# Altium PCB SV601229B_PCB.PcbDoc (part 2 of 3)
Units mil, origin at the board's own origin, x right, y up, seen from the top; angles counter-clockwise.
Board outline 3875 x 2375 mil, 10 copper layers (Top Layer, MidLayer1, MidLayer2, MidLayer3, MidLayer4, MidLayer5, MidLayer6, MidLayer7, MidLayer8, Bottom Layer), stack 98 mil thick; 184 components, 75 nets, 694 pads, 496 vias.
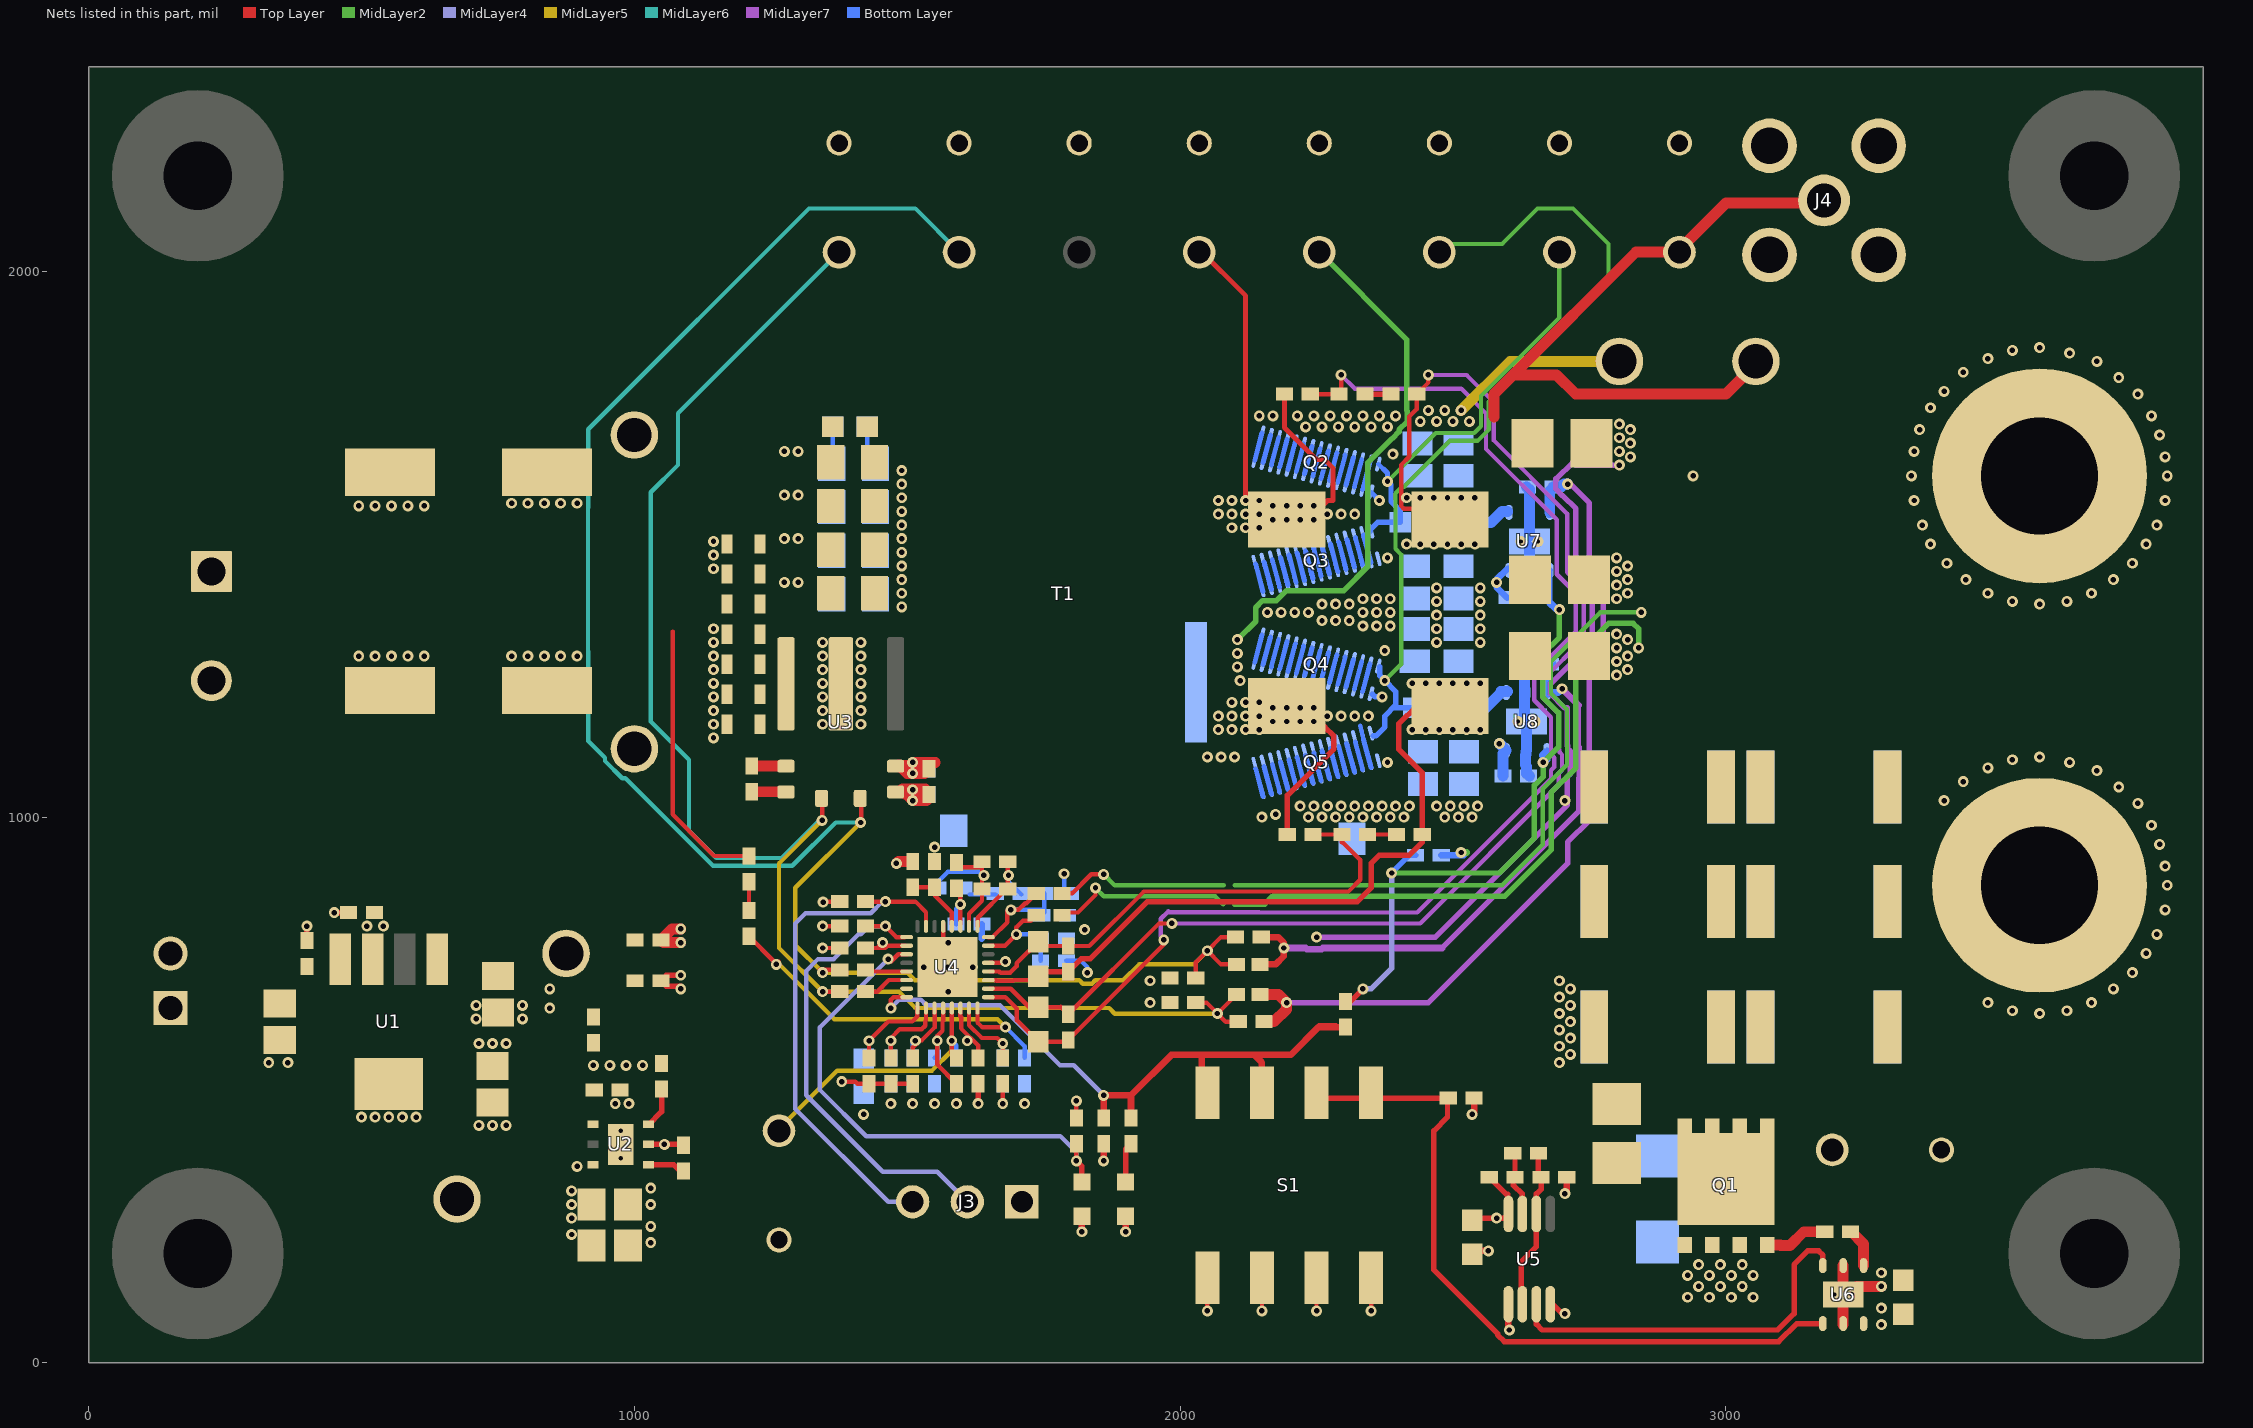
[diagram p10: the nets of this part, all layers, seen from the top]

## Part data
C1 C6 C7 C9 C10: "CAP, CERM, 2.2 µF, 16 V, +/- 10%, X7R, 0805", Cap_Case=0805, Manufacturer=Kemet, Supplier Part Number 1=399-3523-1-ND, TempCo=X7R, Tolerance_%=10, Value1="0.008 ohm", Value2=16V, ValueDisplayed=2.2µF
C2 C19 C53: "CAP, CERM, 0.1 µF, 50 V, +/- 10%, X7R, 0402", Cap_Case=0402, Manufacturer=TDK, Supplier Part Number 1=445-5932-1-ND, TempCo=X7R, Tolerance_%=10, Value1="0.039064 ohm", Value2=50V, ValueDisplayed=0.1µF
C3 C4: "CAP, AL, 22 µF, 100 V, +/- 20%,  ohm, SMD", Cap_Case=HA0, Manufacturer=Chemi-Con, Supplier Part Number 1=565-2160-1-ND, Tolerance_%=20, Value1=Unknown, Value2=100V, ValueDisplayed=22µF
C5 C8 C39 C41 C51: "CAP, CERM, 0.22 µF, 16 V, +/- 10%, X7R, 0402", Cap_Case=0402, Manufacturer=TDK, Supplier Part Number 1=445-5936-1-ND, TempCo=X7R, Tolerance_%=10, Value1=Unknown, Value2=16V, ValueDisplayed=0.22µF
C11 C35: "CAP, CERM, 0.01 µF, 16 V, +/- 10%, X7R, 0402", Cap_Case=0402, Manufacturer=TDK, Supplier Part Number 1=445-1262-1-ND, TempCo=X7R, Tolerance_%=10, Value1="0.0623 ohm", Value2=16V, ValueDisplayed=0.01µF
C12 C13 C14 C15 C16 C17 C18: "CAP, CERM, 0.1uF, 100V, +/-10%, X7R, 0603", Cap_Case=0603, Manufacturer=MuRata, Supplier Part Number 1=490-6439-1-ND, TempCo=X7R, Tolerance_%=10, Value1=Unknown, Value2=100V, ValueDisplayed=0.1µF
C20 C21 C22 C23 C54 C55 C56 C57: "CAP, CERM, 4.7uF, 50V, +/-10%, X5R, 0805", Cap_Case=0805, Manufacturer=TDK, Supplier Part Number 1=445-5980-1-ND, TempCo=X5R, Tolerance_%=10, Value1=Unknown, Value2=50V, ValueDisplayed=4.7µF
C24 C25 C26 C28: "CAP, CERM, 1uF, 10V, +/-10%, X5R, 0402", Cap_Case=0402, Manufacturer=MuRata, Supplier Part Number 1=490-3890-1-ND, TempCo=X5R, Tolerance_%=10, Value1=Unknown, Value2=10V, ValueDisplayed=1µF
C27 C38 C40: "CAP, CERM, 10 pF, 50 V, +/- 5%, C0G/NP0, 0402", Cap_Case=0402, Manufacturer=MuRata, Supplier Part Number 1=81-GRM1555C1H100JA1D, TempCo=C0G/NP0, Tolerance_%=5, Value1=Unknown, Value2=50V, ValueDisplayed=10pF
C29 C30: "CAP, CERM, 0.33 µF, 16 V, +/- 10%, X7R, 0603", Cap_Case=0603, Manufacturer=MuRata, Supplier Part Number 1=490-3294-1-ND, TempCo=X7R, Tolerance_%=10, Value1=Unknown, Value2=16V, ValueDisplayed=0.33µF
C31 C37: "CAP, CERM, 0.22 µF, 16 V, +/- 10%, X7R, 0603", Cap_Case=0603, Manufacturer=Kemet, Supplier Part Number 1=399-5619-1-ND, TempCo=X7R, Tolerance_%=10, Value1=Unknown, Value2=16V, ValueDisplayed=0.22µF
C32 C33 C34 C36: "CAP, TA, 150 µF, 6.3 V, +/- 20%, 0.025 ohm, SMD", Cap_Case=3528-21, Manufacturer=Kemet, Supplier Part Number 1=399-5753-1-ND, Tolerance_%=20, Value1="0.025 ohm", Value2=6.3V, ValueDisplayed=150µF
C42 C43 C44 C45 C46 C47 C48 C49: "CAP, CERM, 47 µF, 10 V, +/- 20%, X5R, 0805", Cap_Case=0805, Manufacturer=MuRata, TempCo=X5R, Tolerance_%=20, Value1=Unknown, Value2=10V, ValueDisplayed=47µF
C50: "CAP, CERM, 680 pF, 25 V, +/- 5%, C0G/NP0, 0402", Cap_Case=0402, Manufacturer=MuRata, Supplier Part Number 1=GRM1555C1E681JA01D-ND, TempCo=C0G/NP0, Tolerance_%=5, Value1=Unknown, Value2=25V, ValueDisplayed=680pF
C52: "CAP, CERM, 4700 pF, 16 V, +/- 10%, X7R, 0402", Cap_Case=0402, Manufacturer=MuRata, Supplier Part Number 1=GRM155R71C472KA01D-ND, TempCo=X7R, Tolerance_%=10, Value1=Unknown, Value2=16V, ValueDisplayed=4700pF
D1 D2: "LED, Green, SMD", Color=Green, Manufacturer="Wurth Elektronik eiSos", Supplier Part Number 1=732-4971-1-ND, Value1=W, Value2=3.2V
D3 D4: "Diode, Schottky, 45 V, 0.1 A, SOD-523", Manufacturer="Diodes Inc.", Supplier Part Number 1=SDM10U45-FDICT-ND, Value1=0.1A, Value2=0.58V
D5: "Diode, Zener, 12 V, 1.5 W, SMA", Manufacturer="ON Semiconductor", Power_W=1.5, Supplier Part Number 1=1SMA5927BT3GOSCT-ND, Value1=1.5W
H1 H2 H3 H4: "Machine Screw, Round, #4-40 x 1/4, Nylon, Philips panhead", DigiKeyPartNumber=H542-ND, Manufacturer="B&F Fastener Supply"
J1: "Terminal Block, 5.08 mm, 2x1, TH", Color=Green, Current_A=17.5, Manufacturer="Phoenix Contact", Supplier Part Number 1=277-1263-ND, Voltage_V=400
J2: "Terminal Block, 2x1, 2.54mm, TH", Manufacturer="TE Connectivity", Supplier Part Number 1=A98333-ND
J3: "Header, 2.54 mm, 3x1, Tin, TH", Manufacturer=Samtec, Supplier Part Number 1=SAM1035-03-ND
J4: "Connector, TH, SMA", Manufacturer="Emerson Network Power", Supplier Part Number 1=J500-ND
J5 J6: "Standard Banana Jack, Uninsulated, 5.5mm", Manufacturer=Keystone, Supplier Part Number 1=575-4K-ND
L1 L2: "Inductor, Shielded Drum Core, Ferrite, 250 nH, 27 A, 0.00037 ohm, SMD", Manufacturer="Wurth Elektronik", Supplier Part Number 1=732-2998-1-ND, Value1="0.00037 ohm", Value2=27A, ValueDisplayed=250nH
LBL1: library part THT-14-423-10, "Thermal Transfer Printable Labels, 0.650\" W x 0.200\" H - 10,000 per roll", Manufacturer=Brady, Supplier Part Number 1=2065596
LOGO1: library part IEC_HighVoltage, "IEC 61010-1 High Voltage Warning"
Logo2 Logo6: library part TI_Logo, "Texas Instrument Corporate Signature"
Logo3: library part FCC_disclaimer, "FCC_disclaimer"
LOGO4: library part IEC_HotSurface, "IEC 61010-1 Hot Surface Warning"
NT1 NT2 NT3 NT4: library part Net-Tie, "Single point connection between nets."
Q1: "MOSFET, N-CH, 25 V, 100 A, SON 5x6mm", Alternate Manufacturer=None, Manufacturer="Texas Instruments", Supplier Part Number 1=296-24517-1-ND, Value1="0.0021 ohm", Value2="14 nC"
Q2 Q3 Q4 Q5: "MOSFET, N-CH, 30 V, 60 A, 6.05x2.3mm", Alternate Manufacturer=None, Manufacturer=EPC, Value1="? ohm", Value2="20 nC"
R1 R2 R3: "RES, 0.1, 1%, 0.125 W, 0402", Manufacturer=Panasonic, Power_W=0.125, Supplier Part Number 1=P.10AKCT-ND, TempCo="300 ppm/C", Tolerance_%=1, Value1=1%, Value2=0.125W, Value_Code=R100, ValueDisplayed=0.1
R4 R8 R9 R27 R28: "RES, 2.74 k, 1%, 0.063 W, 0402", Manufacturer=Vishay-Dale, Power_W=0.063, Supplier Part Number 1=541-2.74KLCT-ND, TempCo="100 ppm/C", Tolerance_%=1, Value1=1%, Value2=0.063W, Value_Code=2k74, ValueDisplayed=2.74k
R5 R6: "RES, 47 k, 5%, 0.063 W, 0402", Manufacturer=Vishay-Dale, Power_W=0.063, Supplier Part Number 1=541-47KJCT-ND, TempCo="200 ppm/C", Tolerance_%=5, Value1=5%, Value2=0.063W, Value_Code=47k0, ValueDisplayed=47k
R7 R55 R57: "RES, 150 k, 1%, 0.1 W, 0603", Manufacturer=Vishay-Dale, Power_W=0.1, Supplier Part Number 1=541-150KHCT-ND, TempCo="100 ppm/C", Tolerance_%=1, Value1=1%, Value2=0.1W, Value_Code=150k
R10 R11 R13 R25 R26 R58 R59 R67 R68: "RES, 10.0, 1%, 0.063 W, 0402", Manufacturer=Vishay-Dale, Power_W=0.063, Supplier Part Number 1=541-10.0LCT-ND, TempCo="100 ppm/C", Tolerance_%=1, Value1=1%, Value2=0.063W, Value_Code=10R0, ValueDisplayed=10.0
R12 R18 R22 R23 R41 R50 R52 R60: "RES, 10.0 k, 1%, 0.063 W, 0402", Manufacturer=Vishay-Dale, Power_W=0.063, Supplier Part Number 1=541-10.0KLCT-ND, TempCo="100 ppm/C", Tolerance_%=1, Value1=1%, Value2=0.063W, Value_Code=10k0, ValueDisplayed=10.0k
R14 R54: "RES, 100 k, 1%, 0.063 W, 0402", Manufacturer=Vishay-Dale, Power_W=0.063, Supplier Part Number 1=541-100KLCT-ND, TempCo="100 ppm/C", Tolerance_%=1, Value1=1%, Value2=0.063W, Value_Code=100k
R15 R31 R32 R33 R56: "RES, 39.2 k, 1%, 0.063 W, 0402", Manufacturer=Vishay-Dale, Power_W=0.063, Supplier Part Number 1=541-39.2KLCT-ND, TempCo="100 ppm/C", Tolerance_%=1, Value1=1%, Value2=0.063W, Value_Code=39k2, ValueDisplayed=39.2k
R16: "RES, 5.11 k, 1%, 0.063 W, 0402", Manufacturer=Vishay-Dale, Power_W=0.063, Supplier Part Number 1=541-5.11KLCT-ND, TempCo="100 ppm/C", Tolerance_%=1, Value1=1%, Value2=0.063W, Value_Code=5k11, ValueDisplayed=5.11k
R17: "RES, 178 k, 1%, 0.063 W, 0402", Manufacturer=Vishay-Dale, Power_W=0.063, Supplier Part Number 1=541-178KLCT-ND, TempCo="100 ppm/C", Tolerance_%=1, Value1=1%, Value2=0.063W, Value_Code=178k
R19 R51 R53: "RES, 24 k, 5%, 0.063 W, 0402", Manufacturer=Vishay-Dale, Power_W=0.063, Supplier Part Number 1=541-24KJCT-ND, TempCo="200 ppm/C", Tolerance_%=5, Value1=5%, Value2=0.063W, Value_Code=24k0, ValueDisplayed=24k
R20 R21: "RES, 20.0 k, 1%, 0.063 W, 0402", Manufacturer=Vishay-Dale, Power_W=0.063, Supplier Part Number 1=541-20.0KLCT-ND, TempCo="100 ppm/C", Tolerance_%=1, Value1=1%, Value2=0.063W, Value_Code=20k0, ValueDisplayed=20.0k
R24: "RES, 470, 5%, 0.063 W, 0402", Manufacturer=Vishay-Dale, Power_W=0.063, Supplier Part Number 1=541-470JCT-ND, TempCo="200 ppm/C", Tolerance_%=5, Value1=5%, Value2=0.063W, Value_Code=470R, ValueDisplayed=470
R29 R30: "RES, 3.32 k, 1%, 0.063 W, 0402", Manufacturer=Vishay-Dale, Power_W=0.063, Supplier Part Number 1=541-3.32KLCT-ND, TempCo="100 ppm/C", Tolerance_%=1, Value1=1%, Value2=0.063W, Value_Code=3k32, ValueDisplayed=3.32k
R34 R35 R36 R37 R38 R39 R42 R43 R44 R45 R46 R47: "RES, 0.04, 1%, 3 W, 2512", Manufacturer=Bourns, Power_W=3, Supplier Part Number 1=CRA2512-FZ-R040ELFCT-ND, TempCo="75 ppm/C", Tolerance_%=1, Value1=1%, Value2=3W, Value_Code=R040, ValueDisplayed=0.04
R40 R61 R62 R63 R64: "RES, 1.00 k, 1%, 0.063 W, 0402", Manufacturer=Vishay-Dale, Power_W=0.063, Supplier Part Number 1=541-1.00KLCT-ND, TempCo="100 ppm/C", Tolerance_%=1, Value1=1%, Value2=0.063W, Value_Code=1k00, ValueDisplayed=1.00k
R48 R49: "RES, 2.2, 5%, 0.1 W, 0603", Manufacturer=Vishay-Dale, Power_W=0.1, Supplier Part Number 1=541-2.2GCT-ND, TempCo="200 ppm/C", Tolerance_%=5, Value1=5%, Value2=0.1W, Value_Code=2R20, ValueDisplayed=2.2
RT1 RT2: "Thermistor NTC, 10k ohm, 5%, 0402", Manufacturer=MuRata, Power_W=0.1, Supplier Part Number 1=490-2414-1-ND, Tolerance_%=5
S1: "Switch, DPST, 2 Pos, 0.1 A, 50 VDC, SMD", CurrentRating_mA=100, Manufacturer="CTS Electrocomponents", Supplier Part Number 1=CT204212ST-ND
T1: library part T_ER18_5to1_A, "Transformer ER18 5:1 turns ratio", Alternate Manufacturer=-, Manufacturer=Ferroxcube
TP1 TP4 TP12: "Test Point, Multipurpose, Black, TH", Manufacturer=Keystone, Supplier Part Number 1=5011K-ND
TP2 TP3 TP14: "Test Point, Multipurpose, Red, TH", Manufacturer=Keystone, Supplier Part Number 1=5010K-ND
TP5 TP6 TP7 TP8 TP9 TP10 TP11 TP13: "PIGTAIL", Manufacturer="Texas Instruments"
TP15 TP16: "Testpoint PCB footprint for pigtail probe", Alternate Manufacturer=-, Manufacturer="Used in BOM report", PartNumber=N/A
U1: "500mA Low Dropout CMOS Linear Regulators Stable with Ceramic Output Capacitors, 5-pin SOT-223, Pb-Free", Manufacturer="Texas Instruments", PackageTopMarking=XYTT*LJZB, PowerWise=Y, Supplier Part Number 1=LP38693MP-5.0TR-ND
U2: "Micropower 250 mA Low-Noise Ultra Low-Dropout Regulator, 6-pin LLP, Pb-Free", Manufacturer="Texas Instruments", PackageTopMarking=ZXYTT*L014A, PowerWise=N, Supplier Part Number 1=LP2992AILD-3.3TR-ND
U3: "80V, 10A GaN Half-Bridge Power Stage, MOF0009A (QFM-9)", Alternate Manufacturer="Texas Instruments", Alternate PartNumber=LMG5200MOFT
U4: "Half-Bridge D-CAP+TM Controller for 48V GaN DC/DC Converter, RSM0032B", Alternate Manufacturer="Texas Instruments"
U5: "CMOS Timer, 8-pin Mini SOIC, Pb-Free", Manufacturer="Texas Instruments", PackageTopMarking=ZXTT*ZC5, PowerWise=N, Supplier Part Number 1=LMC555CMMTR-ND
U6 U7 U8: "Single-Channel High-Speed Low-Side Gate Driver with 4-A Peak Source and 8-A Peak Sink, DRS0006A", Alternate Manufacturer="Texas Instruments", Alternate PartNumber=UCC27512DRST
ZZ1: library part AssemblyNoteLabel, Alternate Manufacturer=-

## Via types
v1: diameter 20, hole 10, Top Layer to Bottom Layer, tented both sides, 459 vias
v2: diameter 20, hole 10, Top Layer to Bottom Layer, 29 vias
v3: diameter 19.68, hole 7.87, Top Layer to Bottom Layer, 8 vias

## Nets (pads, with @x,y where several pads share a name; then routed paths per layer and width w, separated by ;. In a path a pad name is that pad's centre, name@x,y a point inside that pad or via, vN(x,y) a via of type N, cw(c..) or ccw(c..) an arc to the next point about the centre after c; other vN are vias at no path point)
AGND: C1.2 C2.2 C5.1 C6.2 C7.2 C8.1 C9.2 C10.2 C11.2 C24.1 C25.2 C28.1 C31.2 C35.2 C51.2 C52.1 D1.1 D2.1 J2.1 J3.1 NT3.1 NT4.2 R22.2 R23.1 R31.1 R41.2 R50.2 R51.2 R53.2 R54.2 R56.2 R57.1 R62.2 R64.2 TP1.1 TP16.2 U1.5 U2.2 U2.7 U4.29 U4.33 U5.1 | length 559.2
  Top Layer w8: v1(1345,760) C24.1@1376.38,760 ; U4.29@1565.87,803.62 1565.87,743.89 ccw(c1592.75,743.89) v2(1573.74,724.88)
  Top Layer w10: C2.2@400,773.62 v1(400,800) ; v1(450,825) C5.1@476.38,825 ; U2.2@1025.98,400 1085,400 C11.2@1090,395 ; v2(1573.74,724.88) U4.33@1597.36,748.5 ; v1(1630,475) C28.1@1630,511.38
  Top Layer w12: v1(1820,240) D1.1@1820,268.5 ; v1(1860,370) R23.1@1860,401.38 ; v1(1900,240) D2.1@1900,268.5 ; C31.2@2535,200 2540,205 v1(2565,205) ; v1(2535,455) 2538.62,458.62 R31.1@2538.62,485 ; U5.1@2601.61,107.32 2601.61,61.61 v1(2603.23,60) ; v1(2705,310) 2708.62,313.62 C35.2@2708.62,340
  Bottom Layer w12: 1636.73,776.73 C51.2@1636.73,803.62
  other v1: 1030,220 1030,250 1030,290 1030,320 1055,400 715,435 740,435 765,435 500,450 525,450 550,450 575,450 600,450 1420,455 965,475 990,475 1470,475 1510,475 1550,475 1590,475 1715,475 330,550 365,550 710,630 795,630 710,655 795,655 1550,945
  other v2: 1945,660 1575,680 1945,700 1530,725 1620,725 1575,770 1825,793.62
  other v3: 975,375 975,425
CTRL_COMP: C27.1 R16.1 R18.2 R52.2 U4.26 | length 270
  Top Layer w8: R16.1@1590.52,916.73 1599.14,908.1 1636.9,908.1 C27.1@1636.9,868.1 1636.9,846.48 1613.11,822.69 U4.26@1613.11,803.62
  Bottom Layer w8: R52.2@1556.38,870 1556.38,881.38 1574.54,899.54 1634.08,899.54 v1(1640.52,893.1)
CTRL_CSP1: C30.1 R21.2 R27.1 RT1.2 U4.17 | length 2467
  Top Layer w8: U4.17@1652.48,669.76 1679.84,669.76 1700.65,648.95 1700.65,627.85 C30.1@1740,588.5 1792.13,588.5 R21.2@1795,591.38 1970,766.38 v1(1970,775) ; R27.1@2238.62,1775 RT1.2@2285,1775 ; RT1.2@2290,1780 2295,1785 v1(2295,1810)
  MidLayer7 w8: v1(1970,775) 1964.6,780.4 1964.6,813.45 1978.28,827.12 ; 1980,825.4 2144.6,825.4 2145,825 2434.58,825 2679.58,1070 2679.58,1085.73 2685.4,1091.55 2685.4,1108.45 2680.4,1113.45 2680.4,1117.9 2679.58,1118.72 2679.58,1183.01 2648.8,1213.79 2648.8,1263.8 2725,1340 2725,1410 2690,1445 2690,1545 2560.6,1674.4 2560.6,1739.4 2515,1785 2320,1785 v1(2295,1810)
CTRL_CSP2: C29.1 R20.2 R28.1 RT2.2 U4.20 | length 908.6
  Top Layer w8: U4.20@1652.48,717.01 1669.14,717.01 1669.14,715.6 1670.23,715.6 1671.23,714.6 1688.45,714.6 1700.4,726.55 1700.4,731.9 C29.1@1740,771.5 1747.87,763.62 R20.2@1795,763.62 1833.62,763.62 1933.62,863.62 2308.62,863.62 2330,885 2330,921.38 2298.16,953.22 ; R28.1@2243.62,968.03 RT2.2@2296.38,968.03 2296.38,953.22
CTRL_DROOP: C27.2 C50.2 R18.1 U4.25 | length 177.5
  Top Layer w8: U4.25@1628.86,799.68 1629,799.83 1629,815.43 1681.67,868.1 C27.2@1684.14,868.1 R18.1@1684.14,908.1
  Bottom Layer w8: v1(1685.52,893.1) 1685.52,881.73 C50.2@1709.14,858.1
CTRL_EN: R23.2 R24.2 R68.1 S1.1 S1.3 U4.8 | length 1272.3
  Top Layer w8: v1@1470,645 v1(1470,650) 1470,665 1474.76,669.76 U4.8@1495,669.76
  Top Layer w12: R23.2@1860,448.62 v1(1860,490) 1910,490 ; R24.2@1910,448.62 1910,490 ; 2040,560 2040,504.5 S1.1@2050,494.5 ; S1.3@2150,494.5 2150,550 2136,564 ; R68.1@2303.31,615 2286.37,615 ; 1910,490 1984,564 2136,564 ; 2136,564 2202.62,564 2253.63,615 ; 2253.63,615 2286.37,615 ; 2253.63,615 2255,616.38 2285,616.38 2286.37,615
  MidLayer4 w8: v1(1470,650) 1485,665 1525,665 1535,655 1670,655 1780,545 1805,545 v1(1860,490)
CTRL_FREQ: R15.1 R56.1 U4.10 | length 169.2
  Top Layer w8: R15.1@1470,558.62 v1(1470,590) 1470,595 1486,611 1526.36,611 1533.02,617.66 1533.02,625.72 1534.37,627.07 U4.10@1534.37,646.14
  Bottom Layer w8: R56.1@1470,558.62 v1(1470,590)
CTRL_GFB: NT1.1 R58.2 | length 336.2
  Top Layer w8: R58.2@1783.62,820 1788.62,825 1813,825 1845,857 v2(1845,870)
  MidLayer2 w8: v2(1845,870) 1860,855 2064.1,855 NT1.1@2079.1,840
CTRL_IMON: C52.2 R17.2 TP16.1 U4.13 | length 523.8
  Top Layer w8: U4.13@1581.61,646.14 v1(1581.61,590) 1581.61,567.01 R17.2@1590,558.62
  MidLayer5 w8: TP16.1@1265,425 1265,428.85 1371.55,535.4 1545.4,535.4 1581.61,571.61 v1(1581.61,590)
  Bottom Layer w8: v1(1581.61,590) 1590,581.61 C52.2@1590,558.62
CTRL_O_USR: R12.2 R57.2 U4.9 | length 185.1
  Top Layer w8: R12.2@1430,558.62 v2(1430,590) 1465.4,625.4 1509.02,625.4 1518.57,634.94 1518.62,634.94 U4.9@1518.62,650.08
  Bottom Layer w8: R57.2@1430,558.62 v2(1430,590)
CTRL_OCPI: R17.1 R53.1 U4.12 | length 180.8
  Top Layer w8: U4.12@1565.87,646.14 1565.87,627.07 1564.52,625.72 1564.52,608.42 1555,598.91 v1(1555,590) 1555,546.38 R17.1@1590,511.38
  Bottom Layer w8: R53.1@1550,558.62 R53.1@1555,563.62 ; R53.1@1555,570 v1(1555,590)
CTRL_PGOOD: D1.2 R60.1 U4.3 | length 940.4
  Top Layer w8: v2(1465,739.6) 1465,740 1470,735 1483.5,748.5 U4.3@1498.94,748.5 ; v2(1810,370) R60.1@1810,401.38
  Top Layer w10: v2(1810,370) 1820,360 D1.2@1820,331.5
  MidLayer4 w8: v2(1465,739.6) 1340,614.6 1340,500 1425,415 1780.69,415 1810,385.69 v2(1810,370)
CTRL_PWM_HI: R10.2 U4.6 | length 84.1
  Top Layer w8: R10.2@1423.62,680 1445,680 1466.26,701.26 U4.6@1498.94,701.26
CTRL_PWM_LO: R11.2 U4.5 | length 76.6
  Top Layer w8: R11.2@1423.62,720 1426.61,717.01 U4.5@1498.94,717.01
CTRL_RAMP: R14.2 R54.1 U4.11 | length 139.8
  Top Layer w8: R14.2@1510,558.62 1510,578 1523.2,591.2 1526.93,591.2 1550.12,614.39 U4.11@1550.12,646.14
  Bottom Layer w8: R54.1@1510,558.62 1510,585 v1(1515,590)
CTRL_SCL: J3.3 R8.1 U4.31 | length 947.8
  Top Layer w8: R8.1@1423.62,845 v1(1460,845) 1515,845 1534.37,825.63 U4.31@1534.37,803.62
  MidLayer4 w8: v1(1460,845) 1454.64,845 1433.24,823.6 1313.6,823.6 1295,805 1295,465 1465,295 J3.3@1510,295
CTRL_SDA: J3.2 R9.1 U4.1 | length 862.4
  Top Layer w8: R9.1@1423.62,800 v1(1460,800) 1480,780 U4.1@1495,780
  MidLayer4 w8: v1(1460,800) 1430,800 1415,785 1410.8,785 1365.4,739.6 1336.55,739.6 1315,718.05 1315,490 1455,350 1555,350 J3.2@1610,295
CTRL_SKIP: U4.7
CTRL_SLEWA: R19.1 R51.1 U4.15 | length 151.1
  Top Layer w8: U4.15@1613.11,646.14 1613.11,618.65 1636.76,595 1665,595 v1(1675,585) R19.1@1675,558.62
  Bottom Layer w8: R51.1@1675,558.62 v1@1675,580
CTRL_V5A: C25.1 R13.1 U4.28 | length 120.9
  Top Layer w8: R13.1@1510,871.38 C25.1@1550,871.38 1550,856.61 1581.61,825 U4.28@1581.61,803.62
CTRL_VBAT: R6.1 R50.1 U4.16 | length 697.2
  Top Layer w8: R6.1@1210,781.38 1256.38,735 1265,735 v1(1260,730) ; U4.16@1628.86,646.14 1628.86,623.26 1637.12,615 v1(1680,615)
  MidLayer5 w8: v1(1260,730) 1266.15,730 1366.55,629.6 1665.4,629.6 v1(1680,615)
  Bottom Layer w8: v1(1680,615) 1715,580 R50.1@1715,558.62
CTRL_VFB: NT2.1 R59.2 | length 319.2
  Top Layer w8: R59.2@1783.62,860 1802.37,860 1837.37,895 v2(1860,895)
  MidLayer2 w8: v2(1860,895) 1880,875 NT2.1@2080,875
CTRL_VREF: C51.1 R12.1 R14.1 R15.2 R16.2 R19.2 R61.1 R63.1 U4.27 | length 372
  Top Layer w8: v1(1380,515) 1405,515 1408.62,511.38 R15.2@1470,511.38 R14.1@1510,511.38 ; R16.2@1590.52,869.48 1597.36,862.64 v1(1597.36,840) U4.27@1597.36,803.62 ; v1(1675,475) R19.2@1675,511.38
  Bottom Layer w8: C51.1@1589.49,803.62 1589.49,832.13 v1(1597.36,840) ; v2(1787.55,896.07) 1787.55,871.07 R63.1@1798.62,860 R63.1@1800,861.38 ; R61.1@1791.67,736.65 1818.35,736.65 1830,725 v2(1830,715)
DR4: D5.1 Q1.5 Q1.6 Q1.7 Q1.8 Q1.9 R39.1 R44.1 TP15.1
GDRV_1: Q2.1 Q3.1 R48.2 TP11.1 | length 778.1
  MidLayer2 w8: v1(2380,1615) 2468.6,1703.6 2538.86,1703.6 2551.4,1716.14 2551.4,1771.4 2695,1915 TP11.1@2695,2035
  Bottom Layer w8: Q3.1@2349.7,1523.82 Q3.1@2349.7,1527.9 ; Q2.1@2363.26,1646.76 2372.67,1637.35
  Bottom Layer w10: Q3.1@2349.7,1527.9 2361.81,1540 R48.2@2403.5,1540 2403.5,1561.7 2403.3,1561.7 2386.4,1578.6 2386.4,1608.6 v1(2380,1615) 2380,1630.01 2372.67,1637.35
GDRV_2: Q4.1 Q5.1 R49.1 TP10.1 | length 1577.4
  MidLayer2 w8: v1(2375,1250) 2405,1280 2405,1341.15 2405.4,1341.55 2405.4,1408.85 2405,1409.25 2405,1481.15 2394.6,1491.55 2394.6,1593.45 2406.55,1605.4 2410.4,1605.4 2494.2,1689.2 2544.83,1689.2 2565.8,1710.17 2565.8,1760.8 2785,1980 2785,2050 2720,2115 2655,2115 2590,2050 2490,2050 TP10.1@2475,2035
  Bottom Layer w10: Q5.1@2353.89,1148.66 2358.66,1148.66 2375,1165 2375,1185 2395,1205 2395,1230 v1(2375,1250) 2366,1259 Q4.1@2366,1275 ; 2390,1200 R49.1@2428.5,1200
LOAD_TRIG: U5.3 U6.6 | length 701
  Top Layer w10: U5.3@2652.8,107.32 2652.8,70.68 2663.48,60 3095,60 3125,90 3125,180 3150,205 3170,205 3177.6,197.4 U6.6@3177.6,178.15
NetC11_1: C11.1 U2.1 | length 64.2
  Top Layer w10: U2.1@1025.98,362.6 1072.4,362.6 C11.1@1085,350
NetC19_1: C19.1 U3.3 | length 64.9
  Top Layer w20: C19.1@1215,1046.38 1278.94,1046.38 U3.3@1279.61,1047.05
NetC19_2: C19.2 U3.2 | length 64.9
  Top Layer w20: C19.2@1215,1093.62 1278.94,1093.62 U3.2@1279.61,1094.29
NetC35_1: C35.1 R33.1 U5.2 U5.6 | length 287.4
  Top Layer w10: U5.2@2625,110 2625,185 2652.8,212.8 U5.6@2652.8,272.68 2652.8,309.32 2661.38,317.9 C35.1@2661.38,340 ; C35.1@2656.62,341.62 R33.1@2656.62,384
NetC38_1: C38.1 D4.1 R26.2 U7.6 | length 1570.2
  Top Layer w20: D4.1@2145,675 D4.1@2146.65,675 2180,675 v1(2195,660) 2195,647.63 2172.37,625 R26.2@2153.62,625
  MidLayer7 w10: v1(2195,660) 2455,660 2710,915 2710,953.99 2750,993.99 2750,1275 2775,1300 2775,1435 2750,1460 2750,1575 2715,1610 v1(2710,1610)
  Bottom Layer w20: U7.6@2677.4,1558.15 2677.4,1597.4 C38.1@2685,1605 ; C38.1@2683.62,1605 C38.1@2685,1605 ; v1(2710,1610) 2703.43,1610 2698.43,1605 C38.1@2685,1605
NetC40_1: C40.1 D3.1 R25.2 U8.6 | length 1088.4
  Top Layer w12: D3.1@2146.65,730 2175,730 2190,745 v1(2190,760) 2190,770 2180,780 R25.2@2150,780
  MidLayer7 w10: 2480,760 2730,1010 2730,1070.81 2731.6,1072.41 2731.6,1127.59 2730,1129.19 2730,1205
  MidLayer7 w12: v1(2190,760) 2230,760 2232.4,757.6 2259.28,757.6 2261.68,760 2480,760 ; v1(2700,1235) 2730,1205
  Bottom Layer w12: U8.6@2672.4,1228.15 2693.15,1228.15 v1(2700,1235)
  Bottom Layer w20: U8.6@2672.4,1228.15 2672.4,1272.4 C40.1@2680,1280
NetC50_1: C50.1 R52.1 | length 47.8
  Bottom Layer w8: 1614.14,858.1 C50.1@1661.9,858.1
NetD2_2: D2.2 R24.1 | length 74
  Top Layer w10: D2.2@1900,331.5 1900,391.38 R24.1@1910,401.38
NetQ1_4: Q1.4 R40.2 | length 116.2
  Top Layer w20: Q1.4@3075.49,215.7 3100,215.7 ; 3100,215 3117.87,215 3142.87,240 R40.2@3181.38,240
NetR4_1: R4.1 U2.3 | length 76.7
  Top Layer w10: U2.3@1025,435 1050,460 R4.1@1050,501.38
NetR5_1: R5.1 R6.2 | length 52.8
  Top Layer w8: R6.2@1210,828.62 R5.1@1210,881.38
NetR29_2: R29.2 RT1.1 | length 46.4
  Top Layer w10: RT1.1@2338.62,1775 R29.2@2385,1775
NetR30_2: R30.2 RT2.1 | length 52.8
  Top Layer w8: RT2.1@2343.62,968.03 R30.2@2396.38,968.03
NetR31_2: R31.2 S1.5 S1.7 U6.1 | length 1354.9
  Top Layer w10: S1.5@2250,500 2265,485 R31.2@2490,485 ; R31.2@2491.38,485 R31.2@2490,485 ; U6.1@3177.6,71.85 3130.04,71.85 3096.79,38.6 2594.36,38.6 2581.83,51.14 2581.83,53.17 2465,170 2465,425 2490,450 R31.2@2490,485
NetR32_2: R32.2 R33.2 U5.7 | length 121.7
  Top Layer w10: R32.2@2610,345 2610,325.19 2611.33,325.19 2627.2,309.32 U5.7@2627.2,272.68 ; R33.2@2610,380 2613.62,376.38 R32.2@2613.62,340
NetR34_1: R34.1 R37.2
NetR34_2: R34.2 R35.1
NetR35_2: R35.2 R36.1
NetR37_1: R37.1 R38.2
NetR38_1: R38.1 R39.2
NetR40_1: R40.1 U6.4 | length 71.1
  Top Layer w20: R40.1@3230,240 3252.4,217.6 U6.4@3252.4,178.15
NetR42_1: R42.1 R43.2
NetR42_2: R42.2 R45.1
NetR43_1: R43.1 R44.2
NetR45_2: R45.2 R46.1
NetR46_2: R46.2 R47.1
NetR48_1: R48.1 U7.4 | length 141.8
  Bottom Layer w20: R48.1@2466.5,1540 2570,1540 2590,1560 U7.4@2600,1560
NetR49_2: R49.2 U8.4 | length 122.4
  Bottom Layer w20: R49.2@2491.5,1200 2560,1200 2587.57,1227.57 2587.57,1230 U8.4@2600,1230
NetR58_1: R58.1 R61.2 R62.1 U4.23 | length 206.4
  Top Layer w8: U4.23@1648.54,764.25 1679.25,764.25 v2(1700,785) 1700,798 1712,810 1726.38,810 R58.1@1736.38,820
  Bottom Layer w8: v2(1700,785) 1736.07,785 R62.1@1744.42,776.65 R61.2@1744.42,736.65
NetR59_1: R59.1 R63.2 R64.1 U4.24 | length 244
  Top Layer w8: U4.24@1648.54,780 1656.38,780 1683.3,806.93 1683.3,828.3 1690,835 v2(1690,830) 1704.11,830 1716.32,842.21 1718.59,842.21 R59.1@1736.38,860
  Bottom Layer w8: v2(1690,830) R64.1@1751.38,830 ; R64.1@1746.38,820 1751.38,825 R64.1@1751.38,830 ; R63.2@1751.38,860 R64.1@1751.38,830
PGND: C26.2 C53.2 NT4.1 TP5.2 TP6.2 TP7.2 U3.7 | length 258.9
  Top Layer w20: U3.7@1480.39,1094.29 U3.7@1485.71,1094.29 ; U3.7@1485,1095 U3.7@1485.71,1094.29 ; v1(1510,1100) C26.2@1551.38,1100 ; U3.7@1485.71,1094.29 1500,1080 v1(1510,1080) 1531.38,1080 C26.2@1540,1088.62 1534.33,1094.29 U3.7@1485.71,1094.29
  Bottom Layer w10: v1@1513.62,1088.62 1515,1090 1516.38,1088.62 1536.38,1088.62 C53.2@1540,1088.62
  Bottom Layer w20: v1(1510,1080) 1530,1080 C53.2@1535,1085 ; v1(1510,1100) 1525,1100 1536.38,1088.62 C53.2@1540,1085
PWM_H: D4.2 R10.1 R22.1 R26.1 TP5.1 U3.4 | length 2856.3
  Top Layer w8: v1(1344,994) 1344.57,994.57 U3.4@1344.57,1035.24 ; v1(1345,680) R10.1@1376.38,680 ; R22.1@2028.62,660 2048.35,660 v1(2068.35,640) ; D4.2@2103.35,675 v1(2068.35,640) ; R26.1@2106.38,625 2083.35,625 v1(2068.35,640)
  MidLayer5 w8: v1(1344,994) 1265,915 1265,760 v1(1345,680) 1485,680 1515,650 1870,650 1880.4,639.6 2067.95,639.6 v1(2068.35,640)
  MidLayer6 w8: v1@1340,995 1270,925 1150,925 1100,975 1100,1105 1030,1175 1030,1595 1080,1645 1080,1740 TP5.1@1375,2035
PWM_L: D3.2 R11.1 R25.1 R41.1 TP6.1 U3.5 | length 3441.2
  Top Layer w8: v1@1340,720 v1(1345,715) v1@1350,720 ; v1@1345,720 v1@1350,720 ; R11.1@1376.38,720 v1@1350,720 ; v1(1414.65,990) 1415.43,990.79 U3.5@1415.43,1035.24 ; R41.1@2028.62,705 2028.62,733.62 v1(2050,755) ; R25.1@2101.38,780 2075,780 v1(2050,755) ; D3.2@2103.35,730 2075,730 v1(2050,755)
  MidLayer5 w8: v1(1414.65,990) 1295,870.35 1295,765 v1(1345,715) 1345.4,714.6 1500.4,714.6 1514.27,700.73 1815.42,700.73 1821.55,694.6 1838.45,694.6 1844.58,700.73 1895.73,700.73 1925,730 2025,730 v1(2050,755)
  MidLayer6 w8: v1(1414.65,990) 1368.85,990 1289.45,910.6 1144.04,910.6 983.54,1071.1 977.67,1071.1 946.1,1102.67 946.1,1108.54 915.4,1139.24 915.4,1303.85 915,1304.25 915,1566.15 915.4,1566.55 915.4,1710.4 1320,2115 1515,2115 TP6.1@1595,2035
SEC_D1: L1.1 Q2.3 Q2.4 Q2.7 Q2.8 Q2.11 Q2.12 Q2.15 Q2.16 Q2.19 Q2.20 Q2.23 Q2.24 Q2.27 Q2.28 Q3.3 Q3.4 Q3.7 Q3.8 Q3.11 Q3.12 Q3.15 Q3.16 Q3.19 Q3.20 Q3.23 Q3.24 Q3.27 Q3.28 R27.2 T1.3 T1.5 T1.7 T1.9 T1.11 TP8.1 | length 1500
  Top Layer w9: TP8.1@2035,2040 2120,1955 v1(2120,1580) ; R27.2@2191.38,1775 2191.38,1713.62 2250,1655 2265,1655 2280,1640 2280,1580 2270,1580 L1.1@2255,1565
  Bottom Layer w9: Q2.28@2151.96,1649.17 Q2.27@2165.51,1699.74 ; Q3.27@2153.7,1467.59 Q3.28@2167.25,1417.01 ; Q2.24@2182.38,1641.01 Q2.23@2195.93,1691.59 ; Q3.23@2184.12,1475.74 Q3.24@2197.67,1425.17 ; Q2.20@2212.8,1632.86 Q2.19@2226.35,1683.44 ; Q3.19@2214.54,1483.89 Q3.20@2228.1,1433.32 ; Q2.16@2243.22,1624.71 Q2.15@2256.78,1675.29 ; Q3.15@2244.97,1492.05 Q3.16@2258.52,1441.47 ; Q2.12@2273.65,1616.56 Q2.11@2287.2,1667.14 ; Q3.11@2275.39,1500.2 Q3.12@2288.94,1449.62 ; Q2.8@2304.07,1608.41 Q2.7@2317.62,1658.99 ; Q3.7@2305.81,1508.35 Q3.8@2319.37,1457.77 ; Q2.4@2334.49,1600.26 Q2.3@2348.04,1650.83 ; Q3.3@2336.24,1516.5 Q3.4@2349.79,1465.92
  other v1: 2095,1530 2120,1530 2145,1530 2170,1545 2195,1545 2220,1545 2245,1545 2070,1555 2095,1555 2120,1555 2145,1555 2270,1555 2295,1555 2320,1555 2170,1570 2195,1570 2220,1570 2245,1570 2070,1580 2095,1580 2145,1580
SEC_D2: L2.1 Q4.3 Q4.4 Q4.7 Q4.8 Q4.11 Q4.12 Q4.15 Q4.16 Q4.19 Q4.20 Q4.23 Q4.24 Q4.27 Q4.28 Q5.3 Q5.4 Q5.7 Q5.8 Q5.11 Q5.12 Q5.15 Q5.16 Q5.19 Q5.20 Q5.23 Q5.24 Q5.27 Q5.28 R28.2 T1.4 T1.6 T1.8 T1.10 T1.12 TP9.1 | length 1988.8
  Top Layer w10: R28.2@2190,970 2196.38,976.38 2196.38,996.09 2196.4,1039.79 2281.57,1125 2281.73,1125 2281.73,1148.27 2265,1165 L2.1@2260,1165
  MidLayer2 w10: v1(2105,1325) 2138.6,1358.6 2138.6,1383.86 2151.14,1396.4 2176.4,1396.4 2195,1415 2300,1415 2343.6,1458.6 2343.6,1648.86 2388.34,1693.6 2388.86,1693.6 2401.4,1706.14 2401.4,1709.74 2416.4,1724.74 2416.4,1743.86 2415,1745.26 2415,1875 TP9.1@2255,2035
  Bottom Layer w8: 2330,1167.14 Q5.3@2336.24,1141.5
  Bottom Layer w9: Q4.28@2151.96,1279.17 Q4.27@2165.51,1329.74 ; Q5.27@2153.7,1092.59 Q5.28@2167.25,1042.01 ; Q4.24@2182.38,1271.01 Q4.23@2195.93,1321.59 ; Q5.23@2184.12,1100.74 Q5.24@2197.67,1050.17 ; Q4.20@2212.8,1262.86 Q4.19@2226.35,1313.44 ; Q5.19@2214.54,1108.89 2225.92,1066.44 Q5.20@2228.1,1058.32 ; Q4.16@2243.22,1254.71 Q4.15@2256.78,1305.29 ; Q5.15@2244.97,1117.05 2256.34,1074.59 Q5.16@2258.52,1066.47 ; Q4.12@2273.65,1246.56 Q4.11@2287.2,1297.14 ; Q5.11@2275.39,1125.2 2286.77,1082.75 Q5.12@2288.94,1074.62 ; Q4.8@2304.07,1238.41 Q4.7@2317.62,1288.99 ; Q5.7@2305,1135 Q5.8@2319.37,1082.77 ; Q4.4@2334.49,1230.26 Q4.3@2348.04,1280.83 ; Q5.3@2336.24,1141.5 Q5.4@2349.79,1090.92
  other v1: 2050,1110 2075,1110 2100,1110 2070,1160 2095,1160 2120,1160 2145,1160 2170,1175 2195,1175 2220,1175 2245,1175 2070,1185 2095,1185 2120,1185 2145,1185 2270,1185 2295,1185 2320,1185 2345,1185 2170,1200 2195,1200 2220,1200 2245,1200 2095,1210 2120,1210 2145,1210 2110,1250 2105,1275 2105,1300
SEC_GD_EN: R67.2 R68.2 U7.1 U8.1 | length 1228.1
  Top Layer w10: R68.2@2303.31,662.25 2312.25,662.25 v2(2335,685)
  MidLayer2 w10: v2(2387.6,897.4) 2585,897.4 2649.2,961.6 2649.2,1057.95 2665,1073.75 v2(2665,1100) 2693.51,1128.51 2693.51,1190.86 2664.2,1220.17 2664.2,1298.39 2695,1329.19 v2(2695,1380)
  MidLayer4 w10: v2(2335,685) 2350,685 2387.6,722.6 v2(2387.6,897.4)
  Bottom Layer w10: v2(2387.6,897.4) 2420.2,930 R67.2@2431.38,930
  Bottom Layer w12: 2663.28,1112.73 U8.1@2672.4,1121.85 2672.4,1104.94 2667.47,1100 v2(2665,1100) ; U7.1@2677.4,1451.85 2676.54,1450.99 2676.54,1392.32 2687.32,1381.54 v2@2690,1381.54 ; 2680,1391.54 v2@2690,1381.54 ; v2(2695,1380) 2691.54,1380 v2@2690,1381.54
SPGND: C32.2 C33.2 C34.2 C36.2 C37.2 C38.2 C39.1 C40.2 C41.1 C42.2 C43.2 C44.2 C45.2 C46.2 C47.2 C48.2 C49.2 D5.2 J4.2 J4.3 J4.4 J4.5 J6.1 NT1.2 NT3.2 Q1.1 Q1.2 Q1.3 Q2.2 Q2.5 Q2.6 Q2.9 Q2.10 Q2.13 Q2.14 Q2.17 Q2.18 Q2.21 Q2.22 Q2.25 Q2.26 Q2.29 Q2.30 Q3.2 Q3.5 Q3.6 Q3.9 Q3.10 Q3.13 Q3.14 Q3.17 Q3.18 Q3.21 Q3.22 Q3.25 Q3.26 Q3.29 Q3.30 Q4.2 Q4.5 Q4.6 Q4.9 Q4.10 Q4.13 Q4.14 Q4.17 Q4.18 Q4.21 Q4.22 Q4.25 Q4.26 Q4.29 Q4.30 Q5.2 Q5.5 Q5.6 Q5.9 Q5.10 Q5.13 Q5.14 Q5.17 Q5.18 Q5.21 Q5.22 Q5.25 Q5.26 Q5.29 Q5.30 TP8.2 TP9.2 TP10.2 TP11.2 TP12.1 TP13.2 TP15.2 U6.2 U6.5 U6.7 U7.2 U7.5 U7.7 U8.2 U8.5 U8.7 | length 4924.7
  Top Layer w20: U6.2@3215,70 U6.2@3215,71.85 U6.7@3215,125 U6.5@3215,178.15 ; U6.7@3240,140 v1(3285,140)
  MidLayer2 w10: NT1.2@2100,840 2154.71,840 2169.71,855 2595,855 2680,940 2680,1045.2 2725,1090.2 2725,1295 2785,1355 2830,1355 2840,1345 v2(2840,1310)
  MidLayer5 w20: v1(2515,1745) 2605,1835 TP12.1@2805,1835
  MidLayer7 w10: v1(2250,780) 2467.6,780 2709.8,1022.2 2709.8,1073.81 2715.2,1079.21 2715.2,1120.79 2710.2,1125.79 2710.2,1130.24 2709.8,1130.64 2709.8,1200.2 2704.54,1200.2 2678.6,1226.14 2678.6,1243.86 2755,1320.26 2755,1425 2725,1455 2725,1565 2701.4,1588.6 2701.14,1588.6 2688.6,1601.14 2688.6,1620.13 ; 2689.87,1620.13 2719.74,1650 2724.74,1645 v1(2805,1645)
  Bottom Layer w9: Q4.30@2136.74,1283.24 Q4.29@2150.3,1333.82 ; Q2.30@2136.74,1653.24 Q2.29@2150.3,1703.82 ; Q5.29@2138.49,1088.52 Q5.30@2152.04,1037.94 ; Q3.29@2138.49,1463.52 Q3.30@2152.04,1412.94 ; Q4.26@2167.17,1275.09 Q4.25@2180.72,1325.67 ; Q2.26@2167.17,1645.09 Q2.25@2180.72,1695.67 ; Q5.25@2168.91,1096.67 Q5.26@2182.46,1046.09 ; Q3.25@2168.91,1471.67 Q3.26@2182.46,1421.09 ; Q4.22@2197.59,1266.94 Q4.21@2211.14,1317.52 ; Q2.22@2197.59,1636.94 Q2.21@2211.14,1687.52 ; Q5.21@2199.33,1104.82 Q5.22@2212.89,1054.24 ; Q3.21@2199.33,1479.82 Q3.22@2212.89,1429.24 ; Q4.18@2228.01,1258.79 Q4.17@2241.56,1309.36 ; Q2.18@2228.01,1628.79 Q2.17@2241.56,1679.36 ; Q5.17@2229.76,1112.97 Q5.18@2243.31,1062.39 ; Q3.17@2229.76,1487.97 Q3.18@2243.31,1437.39 ; Q4.14@2258.44,1250.63 Q4.13@2271.99,1301.21 ; Q2.14@2258.44,1620.63 Q2.13@2271.99,1671.21 ; Q5.13@2260.18,1121.12 Q5.14@2273.73,1070.54 ; Q3.13@2260.18,1496.12 Q3.14@2273.73,1445.54 ; Q4.10@2288.86,1242.48 Q4.9@2302.41,1293.06 ; Q2.10@2288.86,1612.48 Q2.9@2302.41,1663.06 ; Q5.9@2290.6,1129.27 Q5.10@2304.15,1078.7 ; Q3.9@2290.6,1504.27 Q3.10@2304.15,1453.7 ; Q4.6@2319.28,1234.33 Q4.5@2332.83,1284.91 ; Q2.6@2319.28,1604.33 Q2.5@2332.83,1654.91 ; Q5.5@2321.02,1137.43 Q5.6@2334.58,1086.85 ; Q3.5@2321.02,1512.43 Q3.6@2334.58,1461.85 ; Q2.2@2350,1595 v1(2365,1580) ; U7.2@2640,1450 2640,1408.29 C39.1@2646.31,1401.98
  Bottom Layer w10: Q4.2@2352.15,1225 2357.15,1220 v1(2370,1220)
  Bottom Layer w20: U8.7@2630,1175 2631.38,1176.38 C40.2@2631.38,1280 ; U8.7@2635,1175 U8.2@2635,1121.85 2635,1121.78 2633.6,1120.38 2633.6,1114.73 2632.6,1113.73 2632.6,1095.17 2635,1092.77 2635,1080 C41.1@2640,1075 ; C38.2@2635,1605 2640,1600 U7.5@2640,1558.15 U7.7@2640,1515 ; U7.2@2640,1451.85 U7.7@2640,1495
  other v1: 2930,120 2970,120 3010,120 3050,120 2950,140 2990,140 3030,140 2930,160 2970,160 3010,160 3050,160 3285,165 2950,180 2990,180 3030,180 3575,640 3525,645 3625,645 3480,660 3670,660 3710,685 3745,715 3770,750 3790,785 3805,830 3808.77,875 3805,910 3795,950 3780,985 2150,1000 2235,1000 2260,1000 2285,1000 2310,1000 2335,1000 2360,1000 2385,1000 2410,1000 2485,1000 2510,1000 2535,1000 2175,1005 2220,1020 2245,1020 2270,1020 2295,1020 2320,1020 2345,1020 2370,1020 2395,1020 2420,1020 2470,1020 2495,1020 2520,1020 2545,1020 3755,1025 3400,1030 3720,1055 3435,1065 3680,1085 3480,1090 2380,1100 3630,1100 3525,1105 3575,1110 2800,1260 2820,1270 2800,1285 2820,1295 2375,1305 2470,1320 2550,1320 2800,1335 2470,1345 2550,1345 2335,1350 2360,1350 2385,1350 2260,1360 2285,1360 2310,1360 2470,1370 2550,1370 2160,1375 2185,1375 2210,1375 2235,1375 2335,1375 2360,1375 2385,1375 2260,1390 2285,1390 2310,1390 2470,1395 2550,1395 2335,1400 2360,1400 2385,1400 2800,1400 2820,1410 2470,1420 2550,1420 2800,1425 2820,1435 2800,1450 2820,1460 2380,1475 2800,1475 2825,1660 2390,1665 2805,1670 2825,1685 2805,1695 2825,1710 2230,1715 2260,1715 2290,1715 2320,1715 2350,1715 2380,1715 2805,1720 2440,1725 2470,1725 2500,1725 2530,1725 2145,1735 2170,1735 2215,1735 2245,1735 2275,1735 2305,1735 2335,1735 2365,1735 2395,1735 2455,1745 2485,1745
  other v2: 2705,1030 2800,1310 2820,1325
  other v3: 3199.25,125 3230.75,125 2619.25,1175 2650.75,1175 2624.25,1505 2655.75,1505
V3P3_CTRL: C9.1 C10.1 C24.2 C28.2 R8.2 R9.2 R60.2 S1.2 S1.4 U2.6 U4.2 U4.14 U4.21 | length 442.3
  Top Layer w8: v1(1345,800) R9.2@1376.38,800 ; v1(1346,844) 1345,845 R8.2@1376.38,845 ; C24.2@1423.62,760 1445,760 ; v1(1455,770) 1445,760 ; U4.2@1495,764.25 1464.25,764.25 1460,760 1445,760 ; U4.14@1597.36,650.08 1597.36,634.94 1598.71,633.6 1598.71,612.68 1630,581.39 C28.2@1630,558.62 ; U4.21@1652.48,732.76 1677.76,732.76 v1(1680,735) ; R60.2@1810,448.62 v2(1810,480) ; v1@2050,90 S1.2@2050,155.5 ; v1(2150,95) S1.4@2150,155.5
  other v1: 2050,95 885,235 885,265 885,290 885,315 895,360
  other v2: 1610,590
V5: C5.2 C7.1 C31.1 C37.1 R1.1 R2.1 R3.1 R32.1 S1.6 S1.8 TP2.1 U1.3 U5.4 U5.8 U6.3 | length 307.3
  Top Layer w8: v1@2250,90 S1.6@2250,155.5 ; v1(2350,95) S1.8@2350,155.5
  Top Layer w10: C31.1@2540,265 v1(2580,265) 2593.94,265 U5.8@2600,271.06 ; R32.1@2566.38,340 2597.38,308.99 2600,308.99 U5.8@2600,271.06 ; U5.8@2600,270 U5.8@2600,271.06 ; U5.4@2680,110 2700,90 v1(2705,90)
  other v1: 3285,70 2250,95 3285,100 715,585 740,585 765,585 845,650 845,685 510,800 540,800
V5_CTRL: C8.2 R1.2 R4.2 R13.2 U2.4 | length 31.5
  Top Layer w20: v1(1480,915) 1483.62,918.62 R13.2@1510,918.62
  other v1: 925,545 955,545 985,545 1015,545
V5_GD: C39.2 C41.2 R3.2 R67.1 U7.3 U8.3 | length 278
  Top Layer w10: v1(1085,685) 1085,690 1058.62,690 R3.2@1048.62,700 1058.62,710 v1(1085,710)
  MidLayer2 w12: v2(2515,935) 2525,935
  Bottom Layer w12: R67.1@2478.62,930 2520,930 v2(2515,935) ; C39.2@2599.06,1401.98 2580,1421.05 2580,1435 U7.3@2600,1455
  Bottom Layer w20: v1(2585,1134.45) U8.3@2597.6,1121.85 ; C41.2@2591.38,1075 2591.38,1116.38 U8.3@2595,1120
  other v1: 2580,1430
V5_LM5200: C26.1 C53.1 R2.2 U3.6 | length 359.6
  Top Layer w20: v1(1085,770) 1053.62,770 R2.2@1048.62,775 1068.62,795 v1(1085,795) ; U3.6@1480.39,1047.05 U3.6@1492.95,1047.05 ; U3.6@1491.62,1051.22 C26.1@1533,1051.22 ; C26.1@1540,1035 1535,1030 v1(1510,1030) U3.6@1492.95,1047.05 ; C26.1@1540,1041.38 1534.33,1047.05 U3.6@1492.95,1047.05
  Bottom Layer w10: v1@1506.38,1041.38 1510,1045 1515,1050 1523.62,1041.38 C53.1@1540,1041.38
  Bottom Layer w20: C53.1@1535,1040 1525,1030 v1(1510,1030) 1510,1045 v1(1510,1050) 1515,1050 1530,1050 C53.1@1535,1045
VBIAS_IN: C1.1 C2.1 C6.1 J2.2 U1.1 U1.4
VBUS_N: C3.2 C4.2 C12.2 C13.2 C14.2 C15.2 C16.2 C17.2 C18.2 C54.2 C55.2 C56.2 C57.2 J1.2 R55.1 TP4.1 U3.9 | length 68.8
  Bottom Layer w8: C54.2@1361.64,1647.01 1363.5,1648.87 R55.1@1363.5,1715
  other v1: 1145,1145 1145,1170 1345,1170 1415,1170 1145,1195 1345,1195 1415,1195 1145,1220 1345,1220 1415,1220 1145,1245 1345,1245 1415,1245 1145,1270 1345,1270 1415,1270 775,1295 805,1295 835,1295 865,1295 895,1295 1145,1295 1345,1295 1415,1295 1145,1320 1345,1320 1415,1320 1145,1345 1275,1430 1300,1430 1145,1455 1145,1480 1145,1505 1275,1510 1300,1510 775,1575 805,1575 835,1575 865,1575 895,1575 1275,1590 1300,1590 1275,1670 1300,1670
VBUS_P: C3.1 C4.1 C12.1 C13.1 C14.1 C15.1 C16.1 C17.1 C18.1 C20.1 C21.1 C22.1 C23.1 J1.1 R5.2 R7.2 TP3.1 U3.1 | length 506.6
  Top Layer w8: 1070,1340 1070,1005 1146.38,928.62 R5.2@1210,928.62
  other v1: 495,1295 525,1295 555,1295 585,1295 615,1295 495,1570 525,1570 555,1570 585,1570 615,1570
VOUT: C29.2 C30.2 C32.1 C33.1 C34.1 C36.1 C42.1 C43.1 C44.1 C45.1 C46.1 C47.1 C48.1 C49.1 J4.1 J5.1 L1.2 L2.2 NT2.2 R20.1 R21.1 R29.1 R30.1 R36.2 R47.2 TP13.1 TP14.1 U4.18 U4.19 | length 6199.4
  Top Layer w8: U4.18@1652.48,685.51 1689.49,685.51 1723.5,651.5 C30.2@1740,651.5 1780.01,651.5 1781.07,652.55 R21.1@1795,638.62 1961.38,805 v1(1985,805) ; U4.19@1652.48,701.26 1663.11,701.26 1663.11,700.2 1694.41,700.2 1695.47,701.26 1732.76,701.26 C29.2@1740,708.5 ; L1.2@2445,1560 2440,1565 2410,1565 2405,1570 2405,1645 2420,1660 2420,1704.2 2419.6,1704.6 2419.6,1733.45 2433.62,1747.47 R29.1@2433.62,1775 2455,1796.38 v1(2455,1810)
  Top Layer w10: C29.2@1740,708.5 1747.87,716.38 R20.1@1795,716.38 1818.62,740 1835,740 1940,845 2325,845 2350,870 2350,915 2365,930 2420,930 2443.62,953.62 2443.62,1081.38 2401,1124 2401,1171 2433.74,1203.74 L2.2@2494.61,1203.74
  Top Layer w20: 2575,1732.66 2575,1775 2610,1810 ; TP13.1@2915,2035 2835,2035 2610,1810 ; TP13.1@2915,2040 3000,2125 J4.1@3170,2125 ; TP14.1@3060,1835 3000,1775 2725,1775 2690,1810 2610,1810
  MidLayer2 w8: NT2.2@2100,875 2590,875 2664.6,949.6 2664.6,1051.58 2708.91,1095.89 2708.91,1197.24 2679.6,1226.55 2679.6,1284.6 2770,1375 v2(2845,1375)
  MidLayer7 w8: v1(1985,805) 2440,805 2693.98,1058.98 2693.98,1079.76 2699.8,1085.59 2699.8,1114.41 2694.8,1119.41 2694.8,1123.86 2693.98,1124.68 2693.98,1188.98 2663.2,1219.76 2663.2,1250.24 2739.6,1326.64 2739.6,1418.62 2709.6,1448.62 2709.6,1555.4 2575,1690 2575,1760 2525,1810 v1(2455,1810)
  other v1: 2695,550 2715,565 2695,580 2715,595 2695,610 2715,625 2695,640 2715,655 2695,670 2715,685 2695,700 2425,1160 2450,1160 2475,1160 2500,1160 2525,1160 2550,1160 2425,1245 2450,1245 2475,1245 2500,1245 2525,1245 2550,1245 3575,1390 3525,1395 3625,1395 3480,1410 3670,1410 3440,1435 3710,1435 3405,1465 3745,1465 2415,1500 2440,1500 2465,1500 2490,1500 2515,1500 2540,1500 3375,1500 3770,1500 3360,1535 3790,1535 3345,1580 3805,1580 2415,1585 2440,1585 2465,1585 2490,1585 2515,1585 2540,1585 2940,1625 3340,1625 3808.77,1625 3805,1660 3345,1670 3795,1700 3355,1710 3780,1735 3375,1750 3755,1775 3400,1780 3720,1805 3435,1815 3680,1835 3480,1840 3630,1850 3525,1855 3575,1860
VPRI_CAP: C20.2 C21.2 C22.2 C23.2 C54.1 C55.1 C56.1 C57.1 R7.1 R55.2 T1.2 | length 74.3
  Bottom Layer w8: R55.2@1426.5,1715 1426.5,1662.16 C54.1@1441.64,1647.01
  other v1: 1490,1385 1490,1410 1490,1435 1490,1460 1490,1485 1490,1510 1490,1535 1490,1560 1490,1585 1490,1610 1490,1635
